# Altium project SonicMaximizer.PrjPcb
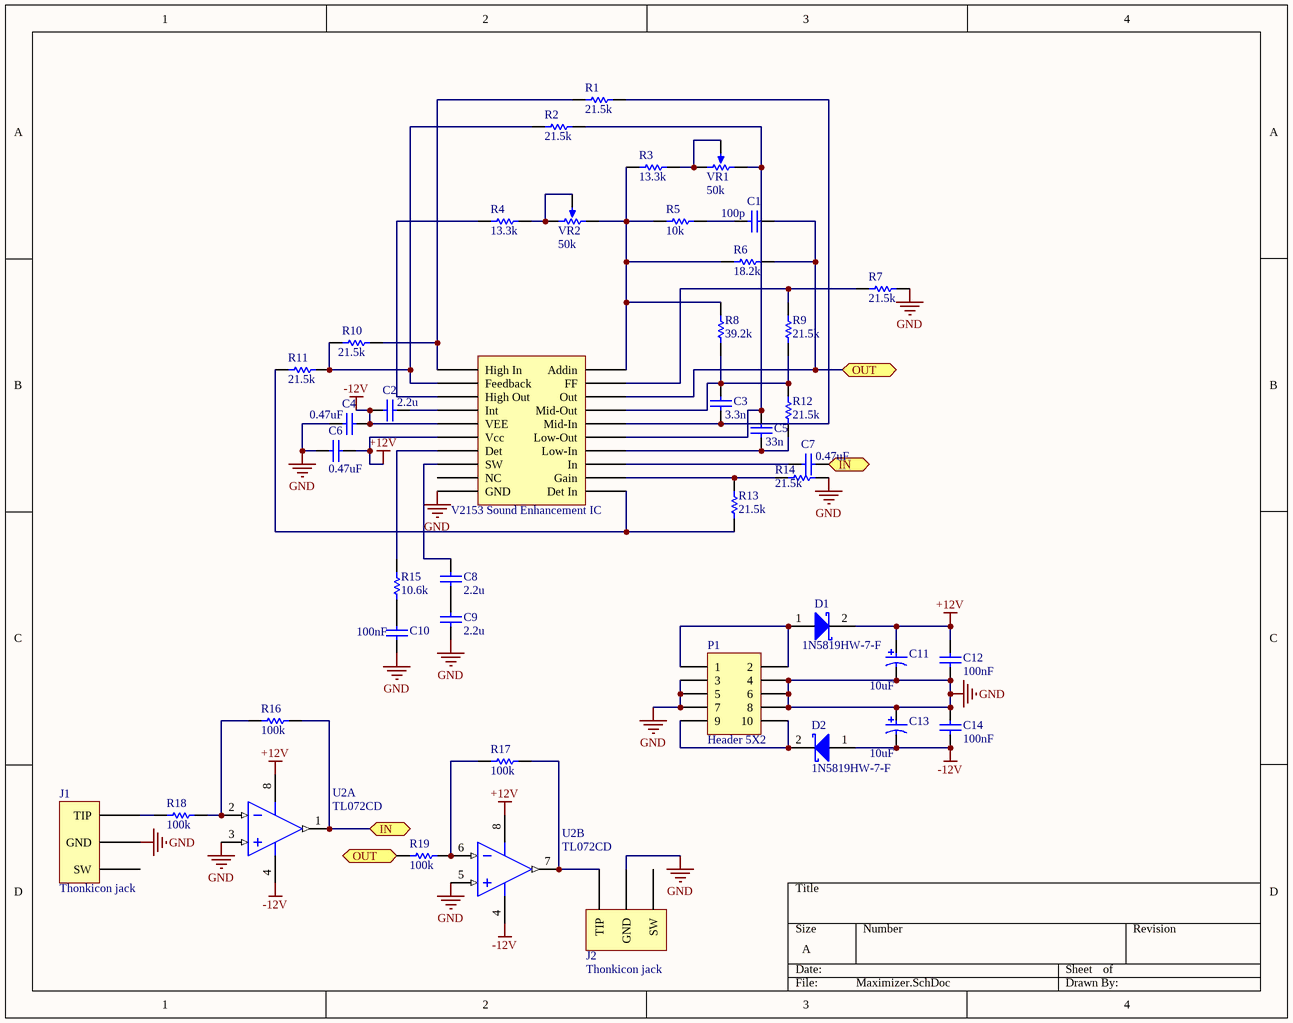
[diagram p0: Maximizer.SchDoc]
1 sheet, 42 parts. Net scope: flat (ports and power ports of the same name join across sheets).
Board file: SoundNicerPCB.PcbDoc

## Sheet Maximizer.SchDoc
size A

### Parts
C1  value 100p  [CAPC0603(1608)100_M]  (hidden comment: 0.)
C2  value 2.2u  [CAPC0603(1608)100_M]  (hidden comment: 0.)
C3  value 3.3n  [CAPC0603(1608)100_M]  (hidden comment: 0.)
C4  0.47uF  [CAPC0603(1608)100_M]
C5  value 33n  [CAPC0603(1608)100_M]  (hidden comment: 0.)
C6  0.47uF  [CAPC0603(1608)100_M]
C7  0.47uF  [CAPC0603(1608)100_M]
C8  value 2.2u  [CAPC0603(1608)100_M]  (hidden comment: 0.)
C9  value 2.2u  [CAPC0603(1608)100_M]  (hidden comment: 0.)
C10  100nF  [CAPC0603(1608)100_M]
C11  10uF  [NIC-CAPA2-4X5.8_V]
C12  100nF  [CAPC0805(2012)75_N]
C13  10uF  [NIC-CAPA2-4X5.8_V]
C14  100nF  [CAPC0805(2012)75_N]
D1  1N5819HW-7-F  [DIOD-SOD-123-2_V]
D2  1N5819HW-7-F  [DIOD-SOD-123-2_V]
J1  Thonkicon jack  [Thonkiconn Pot PJ301M]
J2  Thonkicon jack  [Thonkiconn Pot PJ301M]
P1  Header 5X2  [HDR2X5]
R1  21.5k  [RESC0603(1608)_M]
R2  21.5k  [RESC0603(1608)_M]
R3  13.3k  [RESC0603(1608)_M]
R4  13.3k  [RESC0603(1608)_M]
R5  10k  [RESC0603(1608)_M]
R6  18.2k  [RESC0603(1608)_M]
R7  21.5k  [RESC0603(1608)_M]
R8  39.2k  [RESC0603(1608)_M]
R9  21.5k  [RESC0603(1608)_M]
R10  21.5k  [RESC0603(1608)_M]
R11  21.5k  [RESC0603(1608)_M]
R12  21.5k  [RESC0603(1608)_M]
R13  21.5k  [RESC0603(1608)_M]
R14  21.5k  [RESC0603(1608)_M]
R15  10.6k  [RESC0603(1608)_M]
R16  100k  [RESC0603(1608)_M]
R17  100k  [RESC0603(1608)_M]
R18  100k  [RESC0603(1608)_M]
R19  100k  [RESC0603(1608)_M]
U1  V2153 Sound Enhancement IC  [SOIC20 - duplicate]
U2  TL072CD  [D0008A_M]  (parts A,B of 2)
VR1  50k  [SonGueiPot]
VR2  50k  [SonGueiPot]

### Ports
IN, OUT

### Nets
+12V: C6.2 C11.1 C12.2 D1.2(K) U1.6(Vcc) U2.8(VCC+)
-12V: C2.1 C4.2 C13.2 C14.1 D2.1(A) U1.5(VEE) U2.4(VCC-)
GND: C4.1 C6.1 C9.1 C10.2 C11.2 C12.1 C13.1 C14.2 J1.1(GND) J2.1(GND) P1.3 P1.4 P1.5 P1.6 P1.7 P1.8 R7.1 R14.1 U1.10(GND) U2.3(IN1+) U2.5(IN2+)
NetC1_1: C1.1 R5.1
NetC1_2: C1.2 R6.1 R19.2 U1.18(Out) ; port OUT
NetC2_2: C2.2 U1.4(Int)
NetC3_1: C3.1 R1.1 U1.16(Mid-In)
NetC3_2: C3.2 R8.1 R9.2 R12.1 U1.17(Mid-Out)
NetC5_1: C5.1 R12.2 U1.14(Low-In)
NetC5_2: C5.2 R2.1 U1.15(Low-Out) VR1.3(CW)
NetC7_1: C7.1 U1.13(In)
NetC7_2: C7.2 R16.1 U2.1(OUT1) ; port IN
NetC8_1: C8.1 C9.2
NetC8_2: C8.2 U1.8(SW)
NetC10_1: C10.1 R15.1
NetD1_1: D1.1(A) P1.1 P1.2
NetD2_2: D2.2(K) P1.9 P1.10
NetJ1_3: J1.3(TIP) R18.2
NetJ2_3: J2.3(TIP) R17.1 U2.7(OUT2)
NetR1_2: R1.2 R10.1 U1.1(High_In)
NetR2_2: R2.2 R10.2 R11.1 U1.2(Feedback)
NetR3_1: R3.1 VR1.1(CCW) VR1.2(WIPER)
NetR3_2: R3.2 R5.2 R6.2 R8.2 U1.20(Addin) VR2.3(CW)
NetR4_1: R4.1 VR2.1(CCW) VR2.2(WIPER)
NetR4_2: R4.2 U1.3(High_Out)
NetR7_2: R7.2 R9.1 U1.19(FF)
NetR11_2: R11.2 R13.2 U1.11(Det_In)
NetR13_1: R13.1 R14.2 U1.12(Gain)
NetR15_2: R15.2 U1.7(Det)
NetR16_2: R16.2 R18.1 U2.2(IN1-)
NetR17_2: R17.2 R19.1 U2.6(IN2-)

Not connected (* = marked no-connect by the designer): J1 2(SW); J2 2(SW); U1 9(NC)

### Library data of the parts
C1 = CMP-1035-00002-1: CAP; Mfr: AVX; Mfr_Pn: 06032A101JAT2A; Case-EIA: 0603; Tolderance: 10%
C2 C8 C9 = CMP-1035-00002-1: CAP; Mfr: Murata; Mfr_Pn: GRM188R61E225KA12D; Case-EIA: 0603; Tolderance: 10%
C3 = CMP-1035-00002-1: CAP; Mfr: AVX; Mfr_Pn: 06035A332JAT2A; Case-EIA: 0603; Tolderance: 10%
C4 C6 C7 = CMP-1035-00002-1: CAP; Mfr: Murata; Mfr_Pn: GCM188R71E474KA64J
C5 = CMP-1035-00002-1: CAP; Mfr: Murata; Mfr_Pn: GRM188R71H333KA61D; Case-EIA: 0603; Tolderance: 10%
C10 = CMP-1035-00002-1: CAP; Mfr: AVX; Mfr_Pn: MM035C104KCZ2A
C11 C13 = CMP-0687-00016-1: Aluminum Electrolytic Capacitor, UD Series, Low Impedance, 10 uF, 25 V, + / - 20%, -55 to 105 degC, Chip Type, 4 x 5.8 mm D x L, Pb-Free, Reel; Mfr: Nichicon; Mfr_Pn: UUD1E100MCL1GS
C12 C14 = CMP-1036-00012-1: CAP 0.5pF 25V ±0.1pF 0805 (2012 Metric) Thickness 0.75mm SMD; Mfr: AVX; Mfr_Pn: 08053F102K4T2A
D1 D2 = CMP-0303-00003-1: 1.0 A Surface Mount Schottky Barrier Rectifier, 40 V, -65 to 125 degC, 2-Pin SOD-123 Package, RoHS, Tape and Reel; Mfr: Diodes Inc.
P1 = Header 5X2: Header, 5-Pin, Dual row
R1 R2 R7 R9-R14 = CMP-1012-00002-1: Res; Mfr: Susumu; Mfr_Pn: RG1608P-2152-D-T5; Case-EIA: 0603; Tolerance: 5 %
R3 R4 = CMP-1012-00002-1: Res; Mfr: Susumu; Mfr_Pn: RR0816P-1332-D-13C; Case-EIA: 0603; Tolerance: 5 %
R5 = CMP-1012-00002-1: Res; Mfr: Susumu; Mfr_Pn: RR0816P-103-D; Case-EIA: 0603; Tolerance: 5 %
R6 = CMP-1012-00002-1: Res; Mfr: Susumu; Mfr_Pn: RR0816P-1822-D-26C; Case-EIA: 0603; Tolerance: 5 %
R8 = CMP-1012-00002-1: Res; Mfr: KOA; Mfr_Pn: RK73H1JTTD3922F; Case-EIA: 0603; Tolerance: 5 %
R15 = CMP-1012-00002-1: Res; Mfr: Koa; Mfr_Pn: RN73H1JTTD1062D100; Case-EIA: 0603; Tolerance: 5 %
R16-R19 = CMP-1012-00002-1: Res; Mfr: Susumu; Mfr_Pn: RR0816P-104-D; Case-EIA: 0603; Tolerance: 5 %
U1 = CoolaudioV2153: V2153
U2 = CMP-0017-00467-2: Dual Low-Noise JFET-Input General-Purpose Operational Amplifier, 7 to 36 V, 0 to 70 degC, 8-pin SOIC (D8), Green (RoHS & no Sb/Br); Manufacturer: Texas Instruments; Slew Rate(Typ)(V/us): 13; Total Supply Voltage(Max)(+5V is 5, +/-5V is 10): 36; Rating: Catalog; Sub Family: General Purpose Amplifier, High Supply Voltage Amplifier (>=30V); Total Supply Voltage(Min)(+5V is 5, +/-5V is 10): 7; Vn at 1kHz(Typ)(nV/rtHz): 18; IIB(Max)(pA): 200; Vio (25C)(Max)(mV): 10; Number of Channels: 2; Iq per channel(Max)(mA): 2.5; CMRR(Min)(dB): 70; GBW(Typ)(MHz): 3
VR1 VR2 = CMP-0972-00009-1: Trimming Potentiometer, 5K Ohm +/- 10%, -55 to 125 degC, 3-Pin 19.05 x 4.83 x 6.6 mm THD, Transparent Housing, RoHS; Manufacturer: Bourns; PartNumber: 3006P-7-502ZLF; Resistance (kOhm): 5; Resistance Tolerance: +/- 10%; Rotational Life: 200 Cycles; Number of Turns: 15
